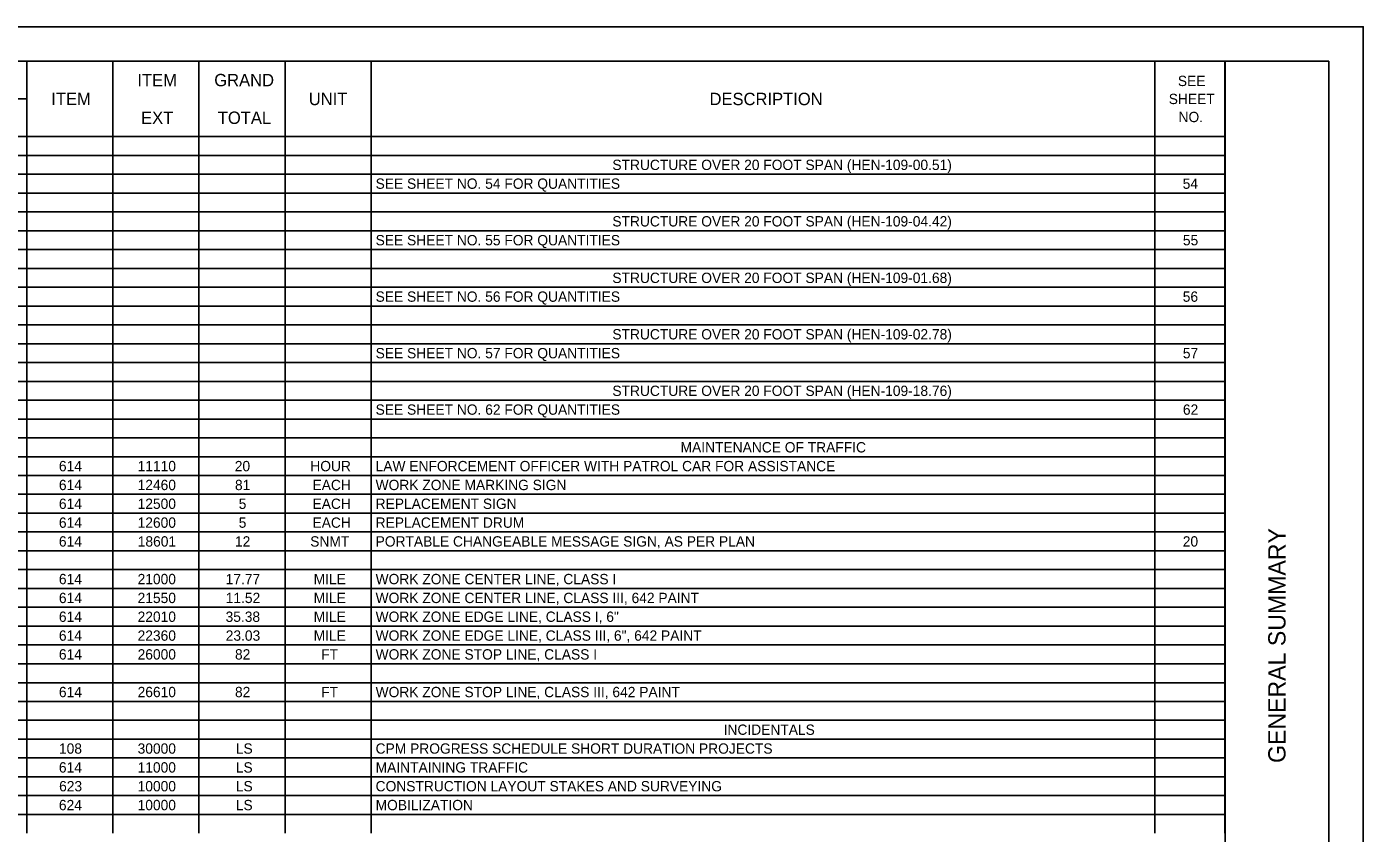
# Model space of a CAD drawing. Extents: x 0 to 34, y 0 to 22.
# Drawn here: x 14.66 to 34, y 10.33 to 22 of the extents above; entities that cross this region are included whole.
import ezdxf

# ---------------------------------------------------------------- set-up
doc = ezdxf.new("R2010")
doc.units = 0
for name, color, linetype in [('Default', 7, 'Continuous'), ('SH_Border', 7, 'Continuous'), ('SH_Cut_Line', 7, 'Continuous'), ('SH_Data', 7, 'Continuous')]:
    doc.layers.add(name, color=color, linetype=linetype)

msp = doc.modelspace()

# ---------------------------------------------------------------- linework, layer by layer
at = {"layer": 'Default'}
for p, q in [((13.647, 21.5), (14.659, 21.5)), ((14.659, 21.5), (15.905, 21.5)), ((14.659, 21.5), (14.659, 21.227)), ((15.905, 21.5), (17.151, 21.5)), ((15.905, 21.5), (15.905, 21.227)), ((17.151, 21.5), (19.643, 21.5)), ((17.151, 21.5), (17.151, 21.227)), ((18.397, 21.5), (18.397, 21.227)), ((19.643, 21.5), (30.985, 21.5)), ((19.643, 21.5), (19.643, 21.227)), ((30.985, 21.5), (31.998, 21.5)), ((30.985, 21.5), (30.985, 21.227)), ((31.998, 21.5), (31.998, 21.227)), ((14.659, 21.227), (14.659, 20.955)), ((15.905, 21.227), (15.905, 20.955)), ((17.151, 21.227), (17.151, 20.955)), ((18.397, 21.227), (18.397, 20.955)), ((19.643, 21.227), (19.643, 20.955)), ((30.985, 21.227), (30.985, 20.955)), ((31.998, 21.227), (31.998, 20.955)), ((13.647, 20.955), (14.659, 20.955)), ((14.659, 20.955), (14.659, 20.682)), ((15.905, 20.955), (15.905, 20.682)), ((17.151, 20.955), (17.151, 20.682)), ((18.397, 20.955), (18.397, 20.682)), ((19.643, 20.955), (19.643, 20.682)), ((30.985, 20.955), (30.985, 20.682)), ((31.998, 20.955), (31.998, 20.682)), ((14.659, 20.682), (14.659, 20.41)), ((15.905, 20.682), (15.905, 20.41)), ((17.151, 20.682), (17.151, 20.41)), ((18.397, 20.682), (18.397, 20.41)), ((19.643, 20.682), (19.643, 20.41)), ((30.985, 20.682), (30.985, 20.41)), ((31.998, 20.682), (31.998, 20.41)), ((13.647, 20.41), (14.659, 20.41)), ((14.659, 20.41), (15.905, 20.41)), ((14.659, 20.41), (14.659, 20.137)), ((15.905, 20.41), (17.151, 20.41)), ((15.905, 20.41), (15.905, 20.137)), ((17.151, 20.41), (19.643, 20.41)), ((17.151, 20.41), (17.151, 20.137)), ((18.397, 20.41), (18.397, 20.137)), ((19.643, 20.41), (30.985, 20.41)), ((19.643, 20.41), (19.643, 20.137)), ((30.985, 20.41), (31.998, 20.41)), ((30.985, 20.41), (30.985, 20.137)), ((31.998, 20.41), (31.998, 20.137)), ((13.647, 20.137), (14.659, 20.137)), ((14.659, 20.137), (15.905, 20.137)), ((14.659, 20.137), (14.659, 18.775)), ((15.905, 20.137), (17.151, 20.137)), ((15.905, 20.137), (15.905, 18.775)), ((17.151, 20.137), (19.643, 20.137)), ((17.151, 20.137), (17.151, 18.775)), ((18.397, 20.137), (18.397, 18.775)), ((19.643, 20.137), (30.985, 20.137)), ((19.643, 20.137), (19.643, 18.775)), ((30.985, 20.137), (31.998, 20.137)), ((30.985, 20.137), (30.985, 18.775)), ((31.998, 20.137), (31.998, 18.775)), ((13.647, 19.865), (14.659, 19.865)), ((14.659, 19.865), (15.905, 19.865)), ((15.905, 19.865), (17.151, 19.865)), ((17.151, 19.865), (19.643, 19.865)), ((19.643, 19.865), (30.985, 19.865)), ((30.985, 19.865), (31.998, 19.865)), ((13.647, 19.592), (14.659, 19.592)), ((14.659, 19.592), (15.905, 19.592)), ((15.905, 19.592), (17.151, 19.592)), ((17.151, 19.592), (19.643, 19.592)), ((19.643, 19.592), (30.985, 19.592)), ((30.985, 19.592), (31.998, 19.592)), ((13.647, 19.32), (14.659, 19.32)), ((14.659, 19.32), (15.905, 19.32)), ((15.905, 19.32), (17.151, 19.32)), ((17.151, 19.32), (19.643, 19.32)), ((19.643, 19.32), (30.985, 19.32)), ((30.985, 19.32), (31.998, 19.32)), ((13.647, 19.047), (14.659, 19.047)), ((14.659, 19.047), (15.905, 19.047)), ((15.905, 19.047), (17.151, 19.047)), ((17.151, 19.047), (19.643, 19.047)), ((19.643, 19.047), (30.985, 19.047)), ((30.985, 19.047), (31.998, 19.047)), ((13.647, 18.775), (14.659, 18.775)), ((14.659, 18.775), (15.905, 18.775)), ((14.659, 18.775), (14.659, 18.23)), ((15.905, 18.775), (17.151, 18.775)), ((15.905, 18.775), (15.905, 18.23)), ((17.151, 18.775), (19.643, 18.775)), ((17.151, 18.775), (17.151, 18.23)), ((18.397, 18.775), (18.397, 18.23)), ((19.643, 18.775), (30.985, 18.775)), ((19.643, 18.775), (19.643, 18.23)), ((30.985, 18.775), (31.998, 18.775)), ((30.985, 18.775), (30.985, 18.23)), ((31.998, 18.775), (31.998, 18.23)), ((13.647, 18.502), (14.659, 18.502)), ((14.659, 18.502), (15.905, 18.502)), ((15.905, 18.502), (17.151, 18.502)), ((17.151, 18.502), (19.643, 18.502)), ((19.643, 18.502), (30.985, 18.502)), ((30.985, 18.502), (31.998, 18.502)), ((13.647, 18.23), (14.659, 18.23)), ((14.659, 18.23), (15.905, 18.23)), ((14.659, 18.23), (14.659, 17.957)), ((15.905, 18.23), (17.151, 18.23)), ((15.905, 18.23), (15.905, 17.957)), ((17.151, 18.23), (19.643, 18.23)), ((17.151, 18.23), (17.151, 17.957)), ((18.397, 18.23), (18.397, 17.957)), ((19.643, 18.23), (30.985, 18.23)), ((19.643, 18.23), (19.643, 17.957)), ((30.985, 18.23), (31.998, 18.23)), ((30.985, 18.23), (30.985, 17.957)), ((31.998, 18.23), (31.998, 17.957)), ((13.647, 17.957), (14.659, 17.957)), ((14.659, 17.957), (15.905, 17.957)), ((14.659, 17.957), (14.659, 17.685)), ((15.905, 17.957), (17.151, 17.957)), ((15.905, 17.957), (15.905, 17.685)), ((17.151, 17.957), (19.643, 17.957)), ((17.151, 17.957), (17.151, 17.685)), ((18.397, 17.957), (18.397, 17.685)), ((19.643, 17.957), (30.985, 17.957)), ((19.643, 17.957), (19.643, 17.685)), ((30.985, 17.957), (31.998, 17.957)), ((30.985, 17.957), (30.985, 17.685)), ((31.998, 17.957), (31.998, 17.685)), ((13.647, 17.685), (14.659, 17.685)), ((14.659, 17.685), (15.905, 17.685)), ((14.659, 17.685), (14.659, 17.412)), ((15.905, 17.685), (17.151, 17.685)), ((15.905, 17.685), (15.905, 17.412)), ((17.151, 17.685), (19.643, 17.685)), ((17.151, 17.685), (17.151, 17.412)), ((18.397, 17.685), (18.397, 17.412)), ((19.643, 17.685), (30.985, 17.685)), ((19.643, 17.685), (19.643, 17.412)), ((30.985, 17.685), (31.998, 17.685)), ((30.985, 17.685), (30.985, 17.412)), ((31.998, 17.685), (31.998, 17.412)), ((13.647, 17.412), (14.659, 17.412)), ((14.659, 17.412), (15.905, 17.412)), ((14.659, 17.412), (14.659, 17.139)), ((15.905, 17.412), (17.151, 17.412)), ((15.905, 17.412), (15.905, 17.139)), ((17.151, 17.412), (19.643, 17.412)), ((17.151, 17.412), (17.151, 17.139)), ((18.397, 17.412), (18.397, 17.139)), ((19.643, 17.412), (30.985, 17.412)), ((19.643, 17.412), (19.643, 17.139)), ((30.985, 17.412), (31.998, 17.412)), ((30.985, 17.412), (30.985, 17.139)), ((31.998, 17.412), (31.998, 17.139)), ((13.647, 17.139), (14.659, 17.139)), ((14.659, 17.139), (15.905, 17.139)), ((14.659, 17.139), (14.659, 16.867)), ((15.905, 17.139), (17.151, 17.139)), ((15.905, 17.139), (15.905, 16.867)), ((17.151, 17.139), (19.643, 17.139)), ((17.151, 17.139), (17.151, 16.867)), ((18.397, 17.139), (18.397, 16.867)), ((19.643, 17.139), (30.985, 17.139)), ((19.643, 17.139), (19.643, 16.867)), ((30.985, 17.139), (31.998, 17.139)), ((30.985, 17.139), (30.985, 16.867)), ((31.998, 17.139), (31.998, 16.867)), ((13.647, 16.867), (14.659, 16.867)), ((14.659, 16.867), (15.905, 16.867)), ((14.659, 16.867), (14.659, 16.322)), ((15.905, 16.867), (17.151, 16.867)), ((15.905, 16.867), (15.905, 16.322)), ((17.151, 16.867), (19.643, 16.867)), ((17.151, 16.867), (17.151, 16.322)), ((18.397, 16.867), (18.397, 16.322)), ((19.643, 16.867), (30.985, 16.867)), ((19.643, 16.867), (19.643, 16.322)), ((30.985, 16.867), (31.998, 16.867)), ((30.985, 16.867), (30.985, 16.322)), ((31.998, 16.867), (31.998, 16.322)), ((13.647, 16.594), (14.659, 16.594)), ((14.659, 16.594), (15.905, 16.594)), ((15.905, 16.594), (17.151, 16.594)), ((17.151, 16.594), (19.643, 16.594)), ((19.643, 16.594), (30.985, 16.594)), ((30.985, 16.594), (31.998, 16.594)), ((13.647, 16.322), (14.659, 16.322)), ((14.659, 16.322), (15.905, 16.322)), ((14.659, 16.322), (14.659, 16.049)), ((15.905, 16.322), (17.151, 16.322)), ((15.905, 16.322), (15.905, 16.049)), ((17.151, 16.322), (19.643, 16.322)), ((17.151, 16.322), (17.151, 16.049)), ((18.397, 16.322), (18.397, 16.049)), ((19.643, 16.322), (30.985, 16.322)), ((19.643, 16.322), (19.643, 16.049)), ((30.985, 16.322), (31.998, 16.322)), ((30.985, 16.322), (30.985, 16.049)), ((31.998, 16.322), (31.998, 16.049)), ((13.647, 16.049), (14.659, 16.049)), ((14.659, 16.049), (15.905, 16.049)), ((14.659, 16.049), (14.659, 15.777)), ((15.905, 16.049), (17.151, 16.049)), ((15.905, 16.049), (15.905, 15.777)), ((17.151, 16.049), (19.643, 16.049)), ((17.151, 16.049), (17.151, 15.777)), ((18.397, 16.049), (18.397, 15.777)), ((19.643, 16.049), (30.985, 16.049)), ((19.643, 16.049), (19.643, 15.777)), ((30.985, 16.049), (31.998, 16.049)), ((30.985, 16.049), (30.985, 15.777)), ((31.998, 16.049), (31.998, 15.777)), ((13.647, 15.777), (14.659, 15.777)), ((14.659, 15.777), (15.905, 15.777)), ((14.659, 15.777), (14.659, 15.504)), ((15.905, 15.777), (17.151, 15.777)), ((15.905, 15.777), (15.905, 15.504)), ((17.151, 15.777), (19.643, 15.777)), ((17.151, 15.777), (17.151, 15.504)), ((18.397, 15.777), (18.397, 15.504)), ((19.643, 15.777), (30.985, 15.777)), ((19.643, 15.777), (19.643, 15.504)), ((30.985, 15.777), (31.998, 15.777)), ((30.985, 15.777), (30.985, 15.504)), ((31.998, 15.777), (31.998, 15.504)), ((13.647, 15.504), (14.659, 15.504)), ((14.659, 15.504), (15.905, 15.504)), ((14.659, 15.504), (14.659, 14.959)), ((15.905, 15.504), (17.151, 15.504)), ((15.905, 15.504), (15.905, 14.959)), ((17.151, 15.504), (19.643, 15.504)), ((17.151, 15.504), (17.151, 14.959)), ((18.397, 15.504), (18.397, 14.959)), ((19.643, 15.504), (30.985, 15.504)), ((19.643, 15.504), (19.643, 14.959)), ((30.985, 15.504), (31.998, 15.504)), ((30.985, 15.504), (30.985, 14.959)), ((31.998, 15.504), (31.998, 14.959)), ((13.647, 15.232), (14.659, 15.232)), ((14.659, 15.232), (15.905, 15.232)), ((15.905, 15.232), (17.151, 15.232)), ((17.151, 15.232), (19.643, 15.232)), ((19.643, 15.232), (30.985, 15.232)), ((30.985, 15.232), (31.998, 15.232)), ((13.647, 14.959), (14.659, 14.959)), ((14.659, 14.959), (15.905, 14.959)), ((14.659, 14.959), (14.659, 14.687)), ((15.905, 14.959), (17.151, 14.959)), ((15.905, 14.959), (15.905, 14.687)), ((17.151, 14.959), (19.643, 14.959)), ((17.151, 14.959), (17.151, 14.687)), ((18.397, 14.959), (18.397, 14.687)), ((19.643, 14.959), (30.985, 14.959)), ((19.643, 14.959), (19.643, 14.687)), ((30.985, 14.959), (31.998, 14.959)), ((30.985, 14.959), (30.985, 14.687)), ((31.998, 14.959), (31.998, 14.687)), ((13.647, 14.687), (14.659, 14.687)), ((14.659, 14.687), (15.905, 14.687)), ((14.659, 14.687), (14.659, 14.414)), ((15.905, 14.687), (17.151, 14.687)), ((15.905, 14.687), (15.905, 14.414)), ((17.151, 14.687), (19.643, 14.687)), ((17.151, 14.687), (17.151, 14.414)), ((18.397, 14.687), (18.397, 14.414)), ((19.643, 14.687), (30.985, 14.687)), ((19.643, 14.687), (19.643, 14.414)), ((30.985, 14.687), (31.998, 14.687)), ((30.985, 14.687), (30.985, 14.414)), ((31.998, 14.687), (31.998, 14.414)), ((13.647, 14.414), (14.659, 14.414)), ((14.659, 14.414), (15.905, 14.414)), ((14.659, 14.414), (14.659, 14.142)), ((15.905, 14.414), (17.151, 14.414)), ((15.905, 14.414), (15.905, 14.142)), ((17.151, 14.414), (19.643, 14.414)), ((17.151, 14.414), (17.151, 14.142)), ((18.397, 14.414), (18.397, 14.142)), ((19.643, 14.414), (30.985, 14.414)), ((19.643, 14.414), (19.643, 14.142)), ((30.985, 14.414), (31.998, 14.414)), ((30.985, 14.414), (30.985, 14.142)), ((31.998, 14.414), (31.998, 14.142)), ((13.647, 14.142), (14.659, 14.142)), ((14.659, 14.142), (15.905, 14.142)), ((14.659, 14.142), (14.659, 11.961)), ((15.905, 14.142), (17.151, 14.142)), ((15.905, 14.142), (15.905, 11.961)), ((17.151, 14.142), (19.643, 14.142)), ((17.151, 14.142), (17.151, 11.961)), ((18.397, 14.142), (18.397, 11.961)), ((19.643, 14.142), (30.985, 14.142)), ((19.643, 14.142), (19.643, 11.961)), ((30.985, 14.142), (31.998, 14.142)), ((30.985, 14.142), (30.985, 11.961)), ((31.998, 14.142), (31.998, 11.961)), ((13.647, 13.869), (14.659, 13.869)), ((14.659, 13.869), (15.905, 13.869)), ((15.905, 13.869), (17.151, 13.869)), ((17.151, 13.869), (19.643, 13.869)), ((19.643, 13.869), (30.985, 13.869)), ((30.985, 13.869), (31.998, 13.869)), ((13.647, 13.597), (14.659, 13.597)), ((14.659, 13.597), (15.905, 13.597)), ((15.905, 13.597), (17.151, 13.597)), ((17.151, 13.597), (19.643, 13.597)), ((19.643, 13.597), (30.985, 13.597)), ((30.985, 13.597), (31.998, 13.597)), ((13.647, 13.324), (14.659, 13.324)), ((14.659, 13.324), (15.905, 13.324)), ((15.905, 13.324), (17.151, 13.324)), ((17.151, 13.324), (19.643, 13.324)), ((19.643, 13.324), (30.985, 13.324)), ((30.985, 13.324), (31.998, 13.324)), ((13.647, 13.052), (14.659, 13.052)), ((14.659, 13.052), (15.905, 13.052)), ((15.905, 13.052), (17.151, 13.052)), ((17.151, 13.052), (19.643, 13.052)), ((19.643, 13.052), (30.985, 13.052)), ((30.985, 13.052), (31.998, 13.052)), ((13.647, 12.779), (14.659, 12.779)), ((14.659, 12.779), (15.905, 12.779)), ((15.905, 12.779), (17.151, 12.779)), ((17.151, 12.779), (19.643, 12.779)), ((19.643, 12.779), (30.985, 12.779)), ((30.985, 12.779), (31.998, 12.779)), ((13.647, 12.506), (14.659, 12.506)), ((14.659, 12.506), (15.905, 12.506)), ((15.905, 12.506), (17.151, 12.506)), ((17.151, 12.506), (19.643, 12.506)), ((19.643, 12.506), (30.985, 12.506)), ((30.985, 12.506), (31.998, 12.506)), ((13.647, 12.234), (14.659, 12.234)), ((14.659, 12.234), (15.905, 12.234)), ((15.905, 12.234), (17.151, 12.234)), ((17.151, 12.234), (19.643, 12.234)), ((19.643, 12.234), (30.985, 12.234)), ((30.985, 12.234), (31.998, 12.234)), ((13.647, 11.961), (14.659, 11.961)), ((14.659, 11.961), (15.905, 11.961)), ((14.659, 11.961), (14.659, 11.689)), ((15.905, 11.961), (17.151, 11.961)), ((15.905, 11.961), (15.905, 11.689)), ((17.151, 11.961), (19.643, 11.961)), ((17.151, 11.961), (17.151, 11.689)), ((18.397, 11.961), (18.397, 11.689)), ((19.643, 11.961), (30.985, 11.961)), ((19.643, 11.961), (19.643, 11.689)), ((30.985, 11.961), (31.998, 11.961)), ((30.985, 11.961), (30.985, 11.689)), ((31.998, 11.961), (31.998, 11.689)), ((13.647, 11.689), (14.659, 11.689)), ((14.659, 11.689), (15.905, 11.689)), ((14.659, 11.689), (14.659, 10.599)), ((15.905, 11.689), (17.151, 11.689)), ((15.905, 11.689), (15.905, 10.599)), ((17.151, 11.689), (19.643, 11.689)), ((17.151, 11.689), (17.151, 10.599)), ((18.397, 11.689), (18.397, 10.599)), ((19.643, 11.689), (30.985, 11.689)), ((19.643, 11.689), (19.643, 10.599)), ((30.985, 11.689), (31.998, 11.689)), ((30.985, 11.689), (30.985, 10.599)), ((31.998, 11.689), (31.998, 10.599)), ((13.647, 11.416), (14.659, 11.416)), ((14.659, 11.416), (15.905, 11.416)), ((15.905, 11.416), (17.151, 11.416)), ((17.151, 11.416), (19.643, 11.416)), ((19.643, 11.416), (30.985, 11.416)), ((30.985, 11.416), (31.998, 11.416)), ((13.647, 11.144), (14.659, 11.144)), ((14.659, 11.144), (15.905, 11.144)), ((15.905, 11.144), (17.151, 11.144)), ((17.151, 11.144), (19.643, 11.144)), ((19.643, 11.144), (30.985, 11.144)), ((30.985, 11.144), (31.998, 11.144)), ((13.647, 10.871), (14.659, 10.871)), ((14.659, 10.871), (15.905, 10.871)), ((15.905, 10.871), (17.151, 10.871)), ((17.151, 10.871), (19.643, 10.871)), ((19.643, 10.871), (30.985, 10.871)), ((30.985, 10.871), (31.998, 10.871)), ((13.647, 10.599), (14.659, 10.599)), ((14.659, 10.599), (15.905, 10.599)), ((14.659, 10.599), (14.659, 10.326)), ((15.905, 10.599), (17.151, 10.599)), ((15.905, 10.599), (15.905, 10.326)), ((17.151, 10.599), (19.643, 10.599)), ((17.151, 10.599), (17.151, 10.326)), ((18.397, 10.599), (18.397, 10.326)), ((19.643, 10.599), (30.985, 10.599)), ((19.643, 10.599), (19.643, 10.326)), ((30.985, 10.599), (31.998, 10.599)), ((30.985, 10.599), (30.985, 10.326)), ((31.998, 10.599), (31.998, 10.326))]:
    msp.add_line(p, q, dxfattribs=at)
at = {"layer": 'SH_Border'}
msp.add_line((32, 0.5), (32, 21.5), dxfattribs=at)
msp.add_lwpolyline([(1.5, 21.5), (33.5, 21.5), (33.5, 0.5), (1.5, 0.5)], close=True, dxfattribs=at)
at = {"layer": 'SH_Cut_Line'}
msp.add_lwpolyline([(0, 0), (34, 0), (34, 22), (0, 22)], close=True, dxfattribs=at)

# ---------------------------------------------------------------- texts
at = {"layer": 'Default'}
for s, height, p in [('ITEM', 0.1791, (16.261, 21.138)), ('GRAND', 0.1791, (17.373, 21.138)), ('SEE ', 0.1492, (31.317, 21.141)), ('ITEM', 0.1791, (15.015, 20.865)), ('UNIT', 0.1791, (18.741, 20.865)), ('DESCRIPTION', 0.17909, (24.54, 20.865)), ('SHEET ', 0.1492, (31.185, 20.88)), ('EXT', 0.1791, (16.314, 20.593)), ('TOTAL', 0.1791, (17.424, 20.593)), ('NO.', 0.1492, (31.327, 20.619)), ('STRUCTURE OVER 20 FOOT SPAN (HEN-109-00.51)', 0.14924, (23.134, 19.926)), ('SEE SHEET NO. 54 FOR QUANTITIES', 0.14924, (19.708, 19.654)), ('54', 0.1492, (31.387, 19.654)), ('STRUCTURE OVER 20 FOOT SPAN (HEN-109-04.42)', 0.14924, (23.134, 19.109)), ('SEE SHEET NO. 55 FOR QUANTITIES', 0.14924, (19.708, 18.836)), ('55', 0.1492, (31.39, 18.836)), ('STRUCTURE OVER 20 FOOT SPAN (HEN-109-01.68)', 0.14924, (23.134, 18.291)), ('SEE SHEET NO. 56 FOR QUANTITIES', 0.14924, (19.708, 18.019)), ('56', 0.1492, (31.388, 18.019)), ('STRUCTURE OVER 20 FOOT SPAN (HEN-109-02.78)', 0.14924, (23.134, 17.474)), ('SEE SHEET NO. 57 FOR QUANTITIES', 0.14924, (19.708, 17.201)), ('57', 0.1492, (31.389, 17.201)), ('STRUCTURE OVER 20 FOOT SPAN (HEN-109-18.76)', 0.14924, (23.134, 16.656)), ('SEE SHEET NO. 62 FOR QUANTITIES', 0.14924, (19.708, 16.384)), ('62', 0.1492, (31.39, 16.384)), ('MAINTENANCE OF TRAFFIC', 0.14924, (24.121, 15.838)), ('614', 0.1492, (15.125, 15.566)), ('11110', 0.1492, (16.264, 15.566)), ('20', 0.1492, (17.67, 15.566)), ('HOUR', 0.1492, (18.763, 15.566)), ('LAW ENFORCEMENT OFFICER WITH PATROL CAR FOR ASSISTANCE', 0.14924, (19.708, 15.566)), ('614', 0.1492, (15.125, 15.293)), ('12460', 0.1492, (16.264, 15.293)), ('81', 0.1492, (17.673, 15.293)), ('EACH', 0.1492, (18.795, 15.293)), ('WORK ZONE MARKING SIGN', 0.14924, (19.708, 15.293)), ('614', 0.1492, (15.125, 15.021)), ('12500', 0.1492, (16.264, 15.021)), ('5', 0.149, (17.727, 15.021)), ('EACH', 0.1492, (18.795, 15.021)), ('REPLACEMENT SIGN', 0.14924, (19.708, 15.021)), ('614', 0.1492, (15.125, 14.748)), ('12600', 0.1492, (16.264, 14.748)), ('5', 0.149, (17.727, 14.748)), ('EACH', 0.1492, (18.795, 14.748)), ('REPLACEMENT DRUM', 0.14924, (19.708, 14.748)), ('614', 0.1492, (15.125, 14.476)), ('18601', 0.1492, (16.266, 14.476)), ('12', 0.1492, (17.673, 14.476)), ('SNMT', 0.1492, (18.762, 14.476)), ('PORTABLE CHANGEABLE MESSAGE SIGN, AS PER PLAN', 0.14924, (19.708, 14.476)), ('20', 0.1492, (31.388, 14.476)), ('614', 0.1492, (15.125, 13.931)), ('21000', 0.1492, (16.264, 13.931)), ('17.77', 0.1492, (17.538, 13.931)), ('MILE', 0.1492, (18.812, 13.931)), ('WORK ZONE CENTER LINE, CLASS I', 0.14924, (19.708, 13.931)), ('614', 0.1492, (15.125, 13.658)), ('21550', 0.1492, (16.264, 13.658)), ('11.52', 0.1492, (17.539, 13.658)), ('MILE', 0.1492, (18.812, 13.658)), ('WORK ZONE CENTER LINE, CLASS III, 642 PAINT', 0.14924, (19.708, 13.658)), ('614', 0.1492, (15.125, 13.386)), ('22010', 0.1492, (16.264, 13.386)), ('35.38', 0.1492, (17.537, 13.386)), ('MILE', 0.1492, (18.812, 13.386)), ('WORK ZONE EDGE LINE, CLASS I, 6"', 0.14924, (19.708, 13.386)), ('614', 0.1492, (15.125, 13.113)), ('22360', 0.1492, (16.264, 13.113)), ('23.03', 0.1492, (17.539, 13.113)), ('MILE', 0.1492, (18.812, 13.113)), ('WORK ZONE EDGE LINE, CLASS III, 6", 642 PAINT', 0.14924, (19.708, 13.113)), ('614', 0.1492, (15.125, 12.841)), ('26000', 0.1492, (16.264, 12.841)), ('82', 0.1492, (17.673, 12.841)), ('FT', 0.1492, (18.921, 12.841)), ('WORK ZONE STOP LINE, CLASS I', 0.14924, (19.708, 12.841)), ('614', 0.1492, (15.125, 12.296)), ('26610', 0.1492, (16.264, 12.296)), ('82', 0.1492, (17.673, 12.296)), ('FT', 0.1492, (18.921, 12.296)), ('WORK ZONE STOP LINE, CLASS III, 642 PAINT', 0.14924, (19.708, 12.296)), ('INCIDENTALS', 0.14924, (24.744, 11.751)), ('108', 0.1492, (15.126, 11.478)), ('30000', 0.1492, (16.264, 11.478)), ('LS', 0.1492, (17.685, 11.478)), ('CPM PROGRESS SCHEDULE SHORT DURATION PROJECTS', 0.14924, (19.708, 11.478)), ('614', 0.1492, (15.125, 11.205)), ('11000', 0.1492, (16.264, 11.205)), ('LS', 0.1492, (17.685, 11.205)), ('MAINTAINING TRAFFIC', 0.14924, (19.708, 11.205)), ('623', 0.1492, (15.128, 10.933)), ('10000', 0.1492, (16.264, 10.933)), ('LS', 0.1492, (17.685, 10.933)), ('CONSTRUCTION LAYOUT STAKES AND SURVEYING', 0.14924, (19.708, 10.933)), ('624', 0.1492, (15.125, 10.66)), ('10000', 0.1492, (16.264, 10.66)), ('LS', 0.1492, (17.685, 10.66)), ('MOBILIZATION', 0.14924, (19.708, 10.66))]:
    msp.add_text(s, height=height, dxfattribs=at).set_placement(p)
at = {"layer": 'SH_Data'}
msp.add_text('GENERAL SUMMARY', height=0.25, rotation=90, dxfattribs=at).set_placement((32.875, 11.344))

doc.saveas('drawing.dxf')
